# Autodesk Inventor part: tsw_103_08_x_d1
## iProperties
Created: 2006-03
Part Number: tsw_103_08_x_d1
Document SubType Name: Modeling
Designer: Elise Moss
Author: Elise Moss
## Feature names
1. Base1
